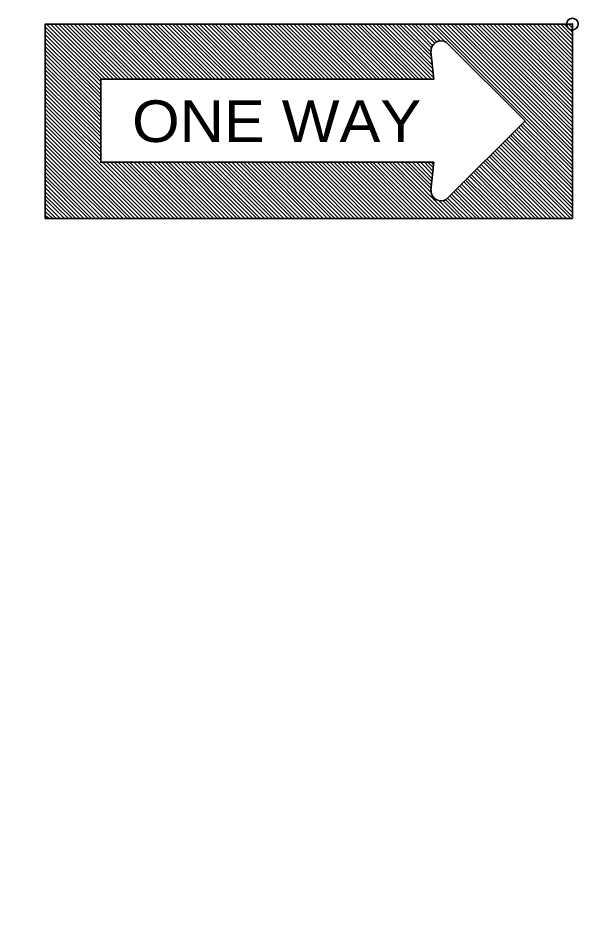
# Model space of a CAD drawing. Extents: x -133 to 547, y -328 to 112.
# Drawn here: x 416.4 to 435.79, y -169.15 to -138.32 of the extents above; entities that cross this region are included whole.
import ezdxf
from ezdxf.enums import TextEntityAlignment as Align

# ---------------------------------------------------------------- set-up
doc = ezdxf.new("R2010")
doc.units = 0
doc.header["$LTSCALE"] = 0.8
doc.header["$PDMODE"] = 32
doc.header["$PDSIZE"] = 0.4
doc.layers.add('1', color=7, linetype='Continuous', lineweight=35)

msp = doc.modelspace()

# ---------------------------------------------------------------- linework, layer by layer
at = {"layer": '1'}
for p, q in [((419.2719, -140.5394), (417.3519, -138.6394)), ((419.3119, -140.4394), (417.3919, -138.5394)), ((419.4319, -140.4394), (417.5319, -138.5394)), ((419.5719, -140.4394), (417.6719, -138.5394)), ((419.7119, -140.4394), (417.8119, -138.5394)), ((419.8519, -140.4394), (417.9519, -138.5394)), ((419.9719, -140.4394), (418.0719, -138.5394)), ((420.1119, -140.4394), (418.2119, -138.5394)), ((420.2519, -140.4394), (418.3519, -138.5394)), ((420.3919, -140.4394), (418.4919, -138.5394)), ((420.5319, -140.4394), (418.6119, -138.5394)), ((420.6519, -140.4394), (418.7519, -138.5394)), ((420.7919, -140.4394), (418.8919, -138.5394)), ((420.9319, -140.4394), (419.0319, -138.5394)), ((421.0719, -140.4394), (419.1719, -138.5394)), ((421.2119, -140.4394), (419.2919, -138.5394)), ((421.3319, -140.4394), (419.4319, -138.5394)), ((421.4719, -140.4394), (419.5719, -138.5394)), ((421.6119, -140.4394), (419.7119, -138.5394)), ((421.7519, -140.4394), (419.8519, -138.5394)), ((421.8719, -140.4394), (419.9719, -138.5394)), ((422.0119, -140.4394), (420.1119, -138.5394)), ((422.1519, -140.4394), (420.2519, -138.5394)), ((422.2919, -140.4394), (420.3919, -138.5394)), ((422.4319, -140.4394), (420.5319, -138.5394)), ((422.5519, -140.4394), (420.6519, -138.5394)), ((422.6919, -140.4394), (420.7919, -138.5394)), ((422.8319, -140.4394), (420.9319, -138.5394)), ((422.9719, -140.4394), (421.0719, -138.5394)), ((423.1119, -140.4394), (421.1919, -138.5394)), ((423.2319, -140.4394), (421.3319, -138.5394)), ((423.3719, -140.4394), (421.4719, -138.5394)), ((423.5119, -140.4394), (421.6119, -138.5394)), ((423.6519, -140.4394), (421.7519, -138.5394)), ((423.7919, -140.4394), (421.8719, -138.5394)), ((423.9119, -140.4394), (422.0119, -138.5394)), ((424.0519, -140.4394), (422.1519, -138.5394)), ((424.1919, -140.4394), (422.2919, -138.5394)), ((424.3319, -140.4394), (422.4319, -138.5394)), ((424.4519, -140.4394), (422.5519, -138.5394)), ((424.5919, -140.4394), (422.6919, -138.5394)), ((424.7319, -140.4394), (422.8319, -138.5394)), ((424.8719, -140.4394), (422.9719, -138.5394)), ((425.0119, -140.4394), (423.1119, -138.5394)), ((425.1319, -140.4394), (423.2319, -138.5394)), ((425.2719, -140.4394), (423.3719, -138.5394)), ((425.4119, -140.4394), (423.5119, -138.5394)), ((425.5519, -140.4394), (423.6519, -138.5394)), ((425.6919, -140.4394), (423.7719, -138.5394)), ((425.8119, -140.4394), (423.9119, -138.5394)), ((425.9519, -140.4394), (424.0519, -138.5394)), ((426.0919, -140.4394), (424.1919, -138.5394)), ((426.2319, -140.4394), (424.3319, -138.5394)), ((426.3719, -140.4394), (424.4519, -138.5394)), ((426.4919, -140.4394), (424.5919, -138.5394)), ((426.6319, -140.4394), (424.7319, -138.5394)), ((426.7719, -140.4394), (424.8719, -138.5394)), ((426.9119, -140.4394), (425.0119, -138.5394)), ((427.0319, -140.4394), (425.1319, -138.5394)), ((427.1719, -140.4394), (425.2719, -138.5394)), ((427.3119, -140.4394), (425.4119, -138.5394)), ((427.4519, -140.4394), (425.5519, -138.5394)), ((427.5919, -140.4394), (425.6719, -138.5394)), ((427.7119, -140.4394), (425.8119, -138.5394)), ((427.8519, -140.4394), (425.9519, -138.5394)), ((427.9919, -140.4394), (426.0919, -138.5394)), ((428.1319, -140.4394), (426.2319, -138.5394)), ((428.2719, -140.4394), (426.3519, -138.5394)), ((428.3919, -140.4394), (426.4919, -138.5394)), ((428.5319, -140.4394), (426.6319, -138.5394)), ((428.6719, -140.4394), (426.7719, -138.5394)), ((428.8119, -140.4394), (426.9119, -138.5394)), ((428.9319, -140.4394), (427.0319, -138.5394)), ((429.0719, -140.4394), (427.1719, -138.5394)), ((429.2119, -140.4394), (427.3119, -138.5394)), ((429.3519, -140.4394), (427.4519, -138.5394)), ((429.4919, -140.4394), (427.5919, -138.5394)), ((429.6119, -140.4394), (427.7119, -138.5394)), ((429.7519, -140.4394), (427.8519, -138.5394)), ((429.8919, -140.4394), (427.9919, -138.5394)), ((430.0319, -140.4394), (428.1319, -138.5394)), ((430.1719, -140.4394), (428.2519, -138.5394)), ((430.2919, -140.4394), (428.3919, -138.5394)), ((430.4319, -140.4394), (428.5319, -138.5394)), ((430.5719, -140.4394), (428.6719, -138.5394)), ((430.7119, -140.4394), (428.8119, -138.5394)), ((430.7719, -140.3794), (428.9319, -138.5394)), ((430.7719, -140.2394), (429.0719, -138.5394)), ((430.7519, -140.0794), (429.2119, -138.5394)), ((430.7319, -139.9394), (429.3519, -138.5394)), ((430.7319, -139.7794), (429.4919, -138.5394)), ((430.7119, -139.6394), (429.6119, -138.5394)), ((430.6919, -139.4994), (429.7519, -138.5394)), ((430.7119, -139.3594), (429.8919, -138.5394)), ((430.7519, -139.2794), (430.0319, -138.5394)), ((430.8319, -139.1994), (430.1519, -138.5394)), ((430.9119, -139.1594), (430.2919, -138.5394)), ((431.0119, -139.1194), (430.4319, -138.5394)), ((431.1719, -139.1394), (430.5719, -138.5394)), ((435.5919, -143.4394), (430.7119, -138.5394)), ((435.5919, -143.2994), (430.8319, -138.5394)), ((435.5919, -143.1594), (430.9719, -138.5394)), ((435.5919, -143.0194), (431.1119, -138.5394)), ((435.5919, -142.8994), (431.2519, -138.5394)), ((435.5919, -142.7594), (431.3919, -138.5394)), ((435.5919, -142.6194), (431.5119, -138.5394)), ((435.5919, -142.4794), (431.6519, -138.5394)), ((435.5919, -142.3394), (431.7919, -138.5394)), ((435.5919, -142.2194), (431.9319, -138.5394)), ((435.5919, -142.0794), (432.0719, -138.5394)), ((435.5919, -141.9394), (432.1919, -138.5394)), ((435.5919, -141.7994), (432.3319, -138.5394)), ((435.5919, -141.6594), (432.4719, -138.5394)), ((435.5919, -141.5394), (432.6119, -138.5394)), ((435.5919, -141.3994), (432.7319, -138.5394)), ((435.5919, -141.2594), (432.8719, -138.5394)), ((435.5919, -141.1194), (433.0119, -138.5394)), ((435.5919, -140.9794), (433.1519, -138.5394)), ((435.5919, -140.8594), (433.2919, -138.5394)), ((435.5919, -140.7194), (433.4119, -138.5394)), ((435.5919, -140.5794), (433.5519, -138.5394)), ((435.5919, -140.4394), (433.6919, -138.5394)), ((435.5919, -140.3194), (433.8319, -138.5394)), ((435.5919, -140.1794), (433.9719, -138.5394)), ((435.5919, -140.0394), (434.0919, -138.5394)), ((435.5919, -139.8994), (434.2319, -138.5394)), ((435.5919, -139.7594), (434.3719, -138.5394)), ((435.5919, -139.6394), (434.5119, -138.5394)), ((435.5919, -139.4994), (434.6519, -138.5394)), ((435.5919, -139.3594), (434.7719, -138.5394)), ((435.5919, -139.2194), (434.9119, -138.5394)), ((435.5919, -139.0794), (435.0519, -138.5394)), ((435.5919, -138.9594), (435.1919, -138.5394)), ((435.5919, -138.8194), (435.3119, -138.5394)), ((435.5919, -138.6794), (435.4519, -138.5394)), ((419.2719, -140.6794), (417.3519, -138.7594)), ((419.2719, -140.8194), (417.3519, -138.8994)), ((419.2719, -140.9594), (417.3519, -139.0394)), ((419.2719, -141.0794), (417.3519, -139.1794)), ((433.9519, -141.8794), (431.2319, -139.1794)), ((419.2719, -141.2194), (417.3519, -139.3194)), ((419.2719, -141.3594), (417.3519, -139.4394)), ((419.2719, -141.4994), (417.3519, -139.5794)), ((419.2719, -141.6394), (417.3519, -139.7194)), ((419.2719, -141.7594), (417.3519, -139.8594)), ((419.2719, -141.8994), (417.3519, -139.9994)), ((419.2719, -142.0394), (417.3519, -140.1194)), ((419.2719, -142.1794), (417.3519, -140.2594)), ((419.2719, -142.3194), (417.3519, -140.3994)), ((419.2719, -142.4394), (417.3519, -140.5394)), ((419.2719, -142.5794), (417.3519, -140.6794)), ((419.2719, -142.7194), (417.3519, -140.7994)), ((419.2719, -142.8594), (417.3519, -140.9394)), ((419.2719, -142.9794), (417.3519, -141.0794)), ((419.2719, -143.1194), (417.3519, -141.2194)), ((419.2719, -143.2594), (417.3519, -141.3394)), ((421.1319, -145.2594), (417.3519, -141.4794)), ((420.9919, -145.2594), (417.3519, -141.6194)), ((420.8519, -145.2594), (417.3519, -141.7594)), ((420.7319, -145.2594), (417.3519, -141.8994)), ((420.5919, -145.2594), (417.3519, -142.0194)), ((431.2319, -144.5994), (433.9519, -141.8794)), ((435.5919, -143.8394), (433.7919, -142.0394)), ((435.5919, -143.6994), (433.8519, -141.9794)), ((435.5919, -143.5594), (433.9319, -141.8994)), ((420.4519, -145.2594), (417.3519, -142.1594)), ((420.3119, -145.2594), (417.3519, -142.2994)), ((435.5919, -144.5194), (433.4519, -142.3794)), ((435.5919, -144.3794), (433.5119, -142.3194)), ((435.5919, -144.2394), (433.5919, -142.2394)), ((435.5919, -144.1194), (433.6519, -142.1794)), ((435.5919, -143.9794), (433.7319, -142.0994)), ((420.1919, -145.2594), (417.3519, -142.4394)), ((420.0519, -145.2594), (417.3519, -142.5794)), ((419.9119, -145.2594), (417.3519, -142.6994)), ((435.5919, -145.0594), (433.1919, -142.6594)), ((435.5919, -144.9194), (433.2519, -142.5794)), ((435.5919, -144.7994), (433.3119, -142.5194)), ((435.5919, -144.6594), (433.3919, -142.4394)), ((419.7719, -145.2594), (417.3519, -142.8394)), ((419.6319, -145.2594), (417.3519, -142.9794)), ((435.1119, -145.2594), (432.8519, -142.9994)), ((435.2519, -145.2594), (432.9119, -142.9194)), ((435.3919, -145.2594), (432.9719, -142.8594)), ((435.5319, -145.2594), (433.0519, -142.7794)), ((435.5919, -145.1994), (433.1119, -142.7194)), ((419.5119, -145.2594), (417.3519, -143.1194)), ((419.3719, -145.2594), (417.3519, -143.2594)), ((421.2719, -145.2594), (419.3319, -143.3194)), ((421.4119, -145.2594), (419.4719, -143.3194)), ((421.5319, -145.2594), (419.6119, -143.3194)), ((421.6719, -145.2594), (419.7319, -143.3194)), ((421.8119, -145.2594), (419.8719, -143.3194)), ((421.9519, -145.2594), (420.0119, -143.3194)), ((422.0919, -145.2594), (420.1519, -143.3194)), ((422.2119, -145.2594), (420.2719, -143.3194)), ((422.3519, -145.2594), (420.4119, -143.3194)), ((422.4919, -145.2594), (420.5519, -143.3194)), ((422.6319, -145.2594), (420.6919, -143.3194)), ((422.7719, -145.2594), (420.8319, -143.3194)), ((422.8919, -145.2594), (420.9519, -143.3194)), ((423.0319, -145.2594), (421.0919, -143.3194)), ((423.1719, -145.2594), (421.2319, -143.3194)), ((423.3119, -145.2594), (421.3719, -143.3194)), ((423.4319, -145.2594), (421.5119, -143.3194)), ((423.5719, -145.2594), (421.6319, -143.3194)), ((423.7119, -145.2594), (421.7719, -143.3194)), ((423.8519, -145.2594), (421.9119, -143.3194)), ((423.9919, -145.2594), (422.0519, -143.3194)), ((424.1119, -145.2594), (422.1919, -143.3194)), ((424.2519, -145.2594), (422.3119, -143.3194)), ((424.3919, -145.2594), (422.4519, -143.3194)), ((424.5319, -145.2594), (422.5919, -143.3194)), ((424.6719, -145.2594), (422.7319, -143.3194)), ((424.7919, -145.2594), (422.8519, -143.3194)), ((424.9319, -145.2594), (422.9919, -143.3194)), ((425.0719, -145.2594), (423.1319, -143.3194)), ((425.2119, -145.2594), (423.2719, -143.3194)), ((425.3319, -145.2594), (423.4119, -143.3194)), ((425.4719, -145.2594), (423.5319, -143.3194)), ((425.6119, -145.2594), (423.6719, -143.3194)), ((425.7519, -145.2594), (423.8119, -143.3194)), ((425.8919, -145.2594), (423.9519, -143.3194)), ((426.0119, -145.2594), (424.0919, -143.3194)), ((426.1519, -145.2594), (424.2119, -143.3194)), ((426.2919, -145.2594), (424.3519, -143.3194)), ((426.4319, -145.2594), (424.4919, -143.3194)), ((426.5719, -145.2594), (424.6319, -143.3194)), ((426.6919, -145.2594), (424.7519, -143.3194)), ((426.8319, -145.2594), (424.8919, -143.3194)), ((426.9719, -145.2594), (425.0319, -143.3194)), ((427.1119, -145.2594), (425.1719, -143.3194)), ((427.2519, -145.2594), (425.3119, -143.3194)), ((427.3719, -145.2594), (425.4319, -143.3194)), ((427.5119, -145.2594), (425.5719, -143.3194)), ((427.6519, -145.2594), (425.7119, -143.3194)), ((427.7919, -145.2594), (425.8519, -143.3194)), ((427.9119, -145.2594), (425.9919, -143.3194)), ((428.0519, -145.2594), (426.1119, -143.3194)), ((428.1919, -145.2594), (426.2519, -143.3194)), ((428.3319, -145.2594), (426.3919, -143.3194)), ((428.4719, -145.2594), (426.5319, -143.3194)), ((428.5919, -145.2594), (426.6719, -143.3194)), ((428.7319, -145.2594), (426.7919, -143.3194)), ((428.8719, -145.2594), (426.9319, -143.3194)), ((429.0119, -145.2594), (427.0719, -143.3194)), ((429.1519, -145.2594), (427.2119, -143.3194)), ((429.2719, -145.2594), (427.3319, -143.3194)), ((429.4119, -145.2594), (427.4719, -143.3194)), ((429.5519, -145.2594), (427.6119, -143.3194)), ((429.6919, -145.2594), (427.7519, -143.3194)), ((429.8319, -145.2594), (427.8919, -143.3194)), ((429.9519, -145.2594), (428.0119, -143.3194)), ((430.0919, -145.2594), (428.1519, -143.3194)), ((430.2319, -145.2594), (428.2919, -143.3194)), ((430.3719, -145.2594), (428.4319, -143.3194)), ((430.4919, -145.2594), (428.5719, -143.3194)), ((430.6319, -145.2594), (428.6919, -143.3194)), ((430.7719, -145.2594), (428.8319, -143.3194)), ((430.9119, -145.2594), (428.9719, -143.3194)), ((431.0519, -145.2594), (429.1119, -143.3194)), ((431.1719, -145.2594), (429.2519, -143.3194)), ((431.3119, -145.2594), (429.3719, -143.3194)), ((431.4519, -145.2594), (429.5119, -143.3194)), ((430.7119, -144.3794), (429.6519, -143.3194)), ((430.7119, -144.2394), (429.7919, -143.3194)), ((430.7119, -144.1194), (429.9119, -143.3194)), ((430.7319, -143.9994), (430.0519, -143.3194)), ((430.7319, -143.8794), (430.1919, -143.3194)), ((430.7519, -143.7394), (430.3319, -143.3194)), ((430.7519, -143.6194), (430.4719, -143.3194)), ((430.7719, -143.4994), (430.5919, -143.3194)), ((430.7719, -143.3794), (430.7319, -143.3194)), ((434.4319, -145.2594), (432.5119, -143.3194)), ((434.5719, -145.2594), (432.5719, -143.2594)), ((434.7119, -145.2594), (432.6319, -143.1994)), ((434.8519, -145.2594), (432.7119, -143.1194)), ((434.9719, -145.2594), (432.7719, -143.0594)), ((419.2319, -145.2594), (417.3519, -143.3794)), ((419.0919, -145.2594), (417.3519, -143.5194)), ((433.8919, -145.2594), (432.2319, -143.5994)), ((434.0319, -145.2594), (432.2919, -143.5394)), ((434.1719, -145.2594), (432.3719, -143.4594)), ((434.3119, -145.2594), (432.4319, -143.3994)), ((418.9519, -145.2594), (417.3519, -143.6594)), ((418.8319, -145.2594), (417.3519, -143.7994)), ((418.6919, -145.2594), (417.3519, -143.9194)), ((433.3519, -145.2594), (431.9519, -143.8794)), ((433.4919, -145.2594), (432.0319, -143.7994)), ((433.6319, -145.2594), (432.0919, -143.7394)), ((433.7519, -145.2594), (432.1719, -143.6594)), ((418.5519, -145.2594), (417.3519, -144.0594)), ((418.4119, -145.2594), (417.3519, -144.1994)), ((432.6719, -145.2594), (431.6119, -144.2194)), ((432.8119, -145.2594), (431.6919, -144.1394)), ((432.9519, -145.2594), (431.7519, -144.0794)), ((433.0719, -145.2594), (431.8319, -143.9994)), ((433.2119, -145.2594), (431.8919, -143.9394)), ((418.2919, -145.2594), (417.3519, -144.3394)), ((418.1519, -145.2594), (417.3519, -144.4794)), ((432.1319, -145.2594), (431.3519, -144.4794)), ((432.2719, -145.2594), (431.4119, -144.4194)), ((432.3919, -145.2594), (431.4919, -144.3394)), ((432.5319, -145.2594), (431.5519, -144.2794)), ((418.0119, -145.2594), (417.3519, -144.5994)), ((417.8719, -145.2594), (417.3519, -144.7394)), ((431.5919, -145.2594), (430.9719, -144.6394)), ((431.7319, -145.2594), (431.1119, -144.6394)), ((431.8519, -145.2594), (431.2119, -144.6194)), ((431.9919, -145.2594), (431.2719, -144.5594)), ((417.7319, -145.2594), (417.3519, -144.8794)), ((417.6119, -145.2594), (417.3519, -145.0194)), ((417.4719, -145.2594), (417.3519, -145.1594))]:
    msp.add_line(p, q, dxfattribs=at)
msp.add_lwpolyline([(435.5919, -138.5394), (417.3519, -138.5394), (417.3519, -145.2594), (435.5919, -145.2594)], close=True, dxfattribs=at)
msp.add_lwpolyline([(430.6919, -139.4994), (430.7919, -140.4394), (419.2719, -140.4394), (419.2719, -143.3194), (430.7919, -143.3194), (430.6919, -144.2794)], dxfattribs=at)
at = {"layer": '1', "lineweight": 53}
msp.add_arc((422.8289, -169.145), 50, 90, 180, dxfattribs=at)
at = {"layer": '1'}
for centre, start, end in [((431.0496, -139.4697), 58.76645, 183.36449), ((431.0496, -144.3033), 176.63551, 301.23355)]:
    msp.add_arc(centre, 0.3492, start, end, dxfattribs=at)
msp.add_point((435.5919, -138.5394), dxfattribs=at)

# ---------------------------------------------------------------- texts
at = {"layer": '1', "width": 1.1}
msp.add_text('ONE WAY', height=1.44, dxfattribs=at).set_placement((425.3575, -142.6177), align=Align.CENTER)

doc.saveas('drawing.dxf')
